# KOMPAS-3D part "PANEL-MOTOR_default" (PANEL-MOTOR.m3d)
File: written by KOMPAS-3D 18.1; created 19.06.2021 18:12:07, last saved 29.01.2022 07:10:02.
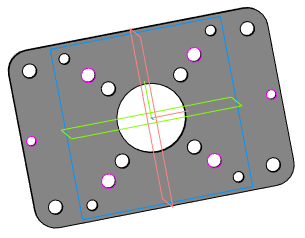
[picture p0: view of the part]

Document properties: Автор: 111; Полное имя файла: C:\Users\admin\Desktop\ffb\PANEL-MOTOR.m3d

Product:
- Part/product: PANEL-MOTOR_default
    Масса: 0.0800166

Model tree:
1. Операция без истории:1
2. Эскиз:2
3. Элемент выдавливания:2
     Расстояние 2 = 3
4. Эскиз:4  (with: Операция без истории:1)
5. Элемент выдавливания:5
     Расстояние 2 = 4.1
